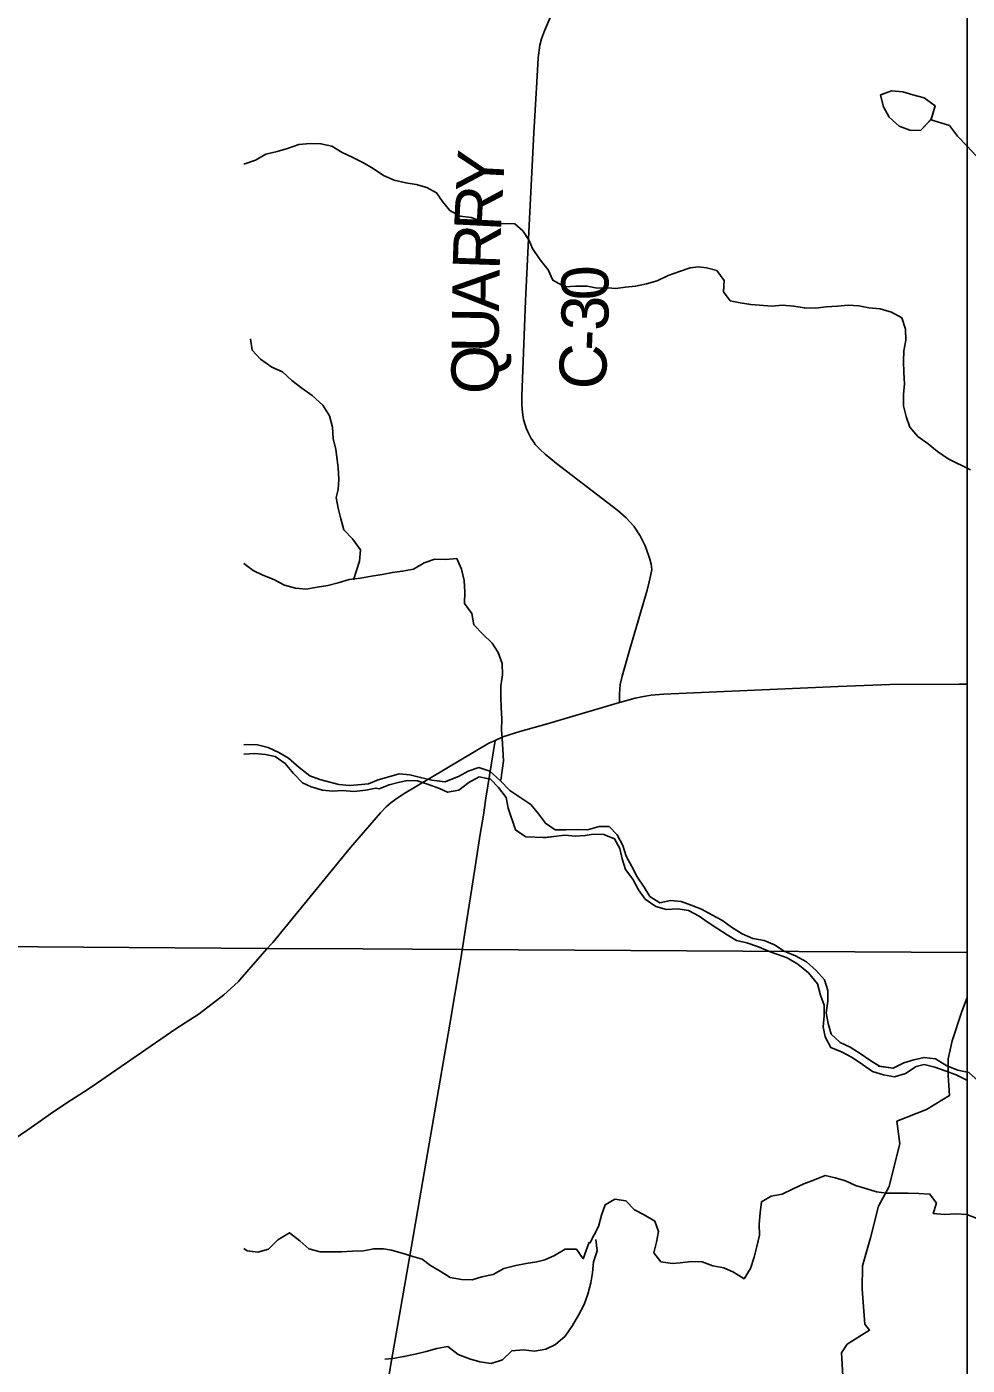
# Model space of a CAD drawing. Extents: x 0 to 34, y 0 to 22.
# Drawn here: x 12.978 to 14.113, y 5.366 to 6.981 of the extents above; entities that cross this region are included whole.
import ezdxf

# ---------------------------------------------------------------- set-up
doc = ezdxf.new("R2010")
doc.units = 0
for name, color, linetype in [('GM_X_Corporation', 7, 'Continuous'), ('GM_X_County_Road', 7, 'Continuous'), ('GM_X_County_Road_Text', 7, 'Continuous'), ('GM_X_Minor_Lake', 7, 'Continuous'), ('GM_X_Minor_River', 7, 'Continuous'), ('GM_X_Rail_Line', 7, 'Continuous'), ('GM_X_State_Route', 7, 'Continuous'), ('SH_Cut_Line', 7, 'Continuous')]:
    doc.layers.add(name, color=color, linetype=linetype)

msp = doc.modelspace()

# ---------------------------------------------------------------- linework, layer by layer
at = {"layer": 'GM_X_Corporation'}
msp.add_lwpolyline([(14.1135, 4.7332), (14.1135, 5.8104), (14.1071, 5.7933), (14.0953, 5.7578), (14.0903, 5.7361), (14.0906, 5.7159), (14.0919, 5.6919), (14.0642, 5.6752), (14.0285, 5.6608), (14.032, 5.6338), (14.0285, 5.6197), (14.0191, 5.5822), (14.0062, 5.5586), (13.9968, 5.5201), (13.9869, 5.4863), (13.9865, 5.4581), (13.9897, 5.416), (13.9956, 5.4089), (13.9686, 5.3919), (13.9616, 5.3814), (13.9633, 5.3538)], dxfattribs=at)
at = {"layer": 'GM_X_County_Road'}
for points in [[(13.5815, 6.4964), (13.5801, 6.5), (13.5779, 6.5076), (13.5765, 6.516), (13.576, 6.5253), (13.576, 6.5362), (13.5803, 6.651), (13.5845, 6.7421), (13.5903, 6.8537), (13.5927, 6.8945), (13.5941, 6.9147), (13.5957, 6.944), (13.5977, 6.9594), (13.5994, 6.9668), (13.603, 6.9764), (13.6163, 7.0074)], [(13.591, 6.4791), (13.587, 6.4847), (13.5829, 6.4928), (13.5815, 6.4964)], [(13.6938, 6.1662), (13.6939, 6.1768), (13.6942, 6.1823), (13.6946, 6.1878), (13.697, 6.1978), (13.7063, 6.2305), (13.727, 6.3017), (13.7297, 6.3116), (13.7316, 6.3205), (13.7326, 6.3267), (13.7319, 6.3329), (13.7304, 6.3389), (13.7288, 6.3441), (13.7247, 6.3553), (13.7185, 6.3673), (13.7109, 6.379), (13.7018, 6.389), (13.6918, 6.3979), (13.6177, 6.4546), (13.6039, 6.4657), (13.598, 6.4716), (13.5921, 6.4774), (13.591, 6.4791)], [(13.5438, 6.1201), (13.553, 6.1246), (13.5733, 6.1311), (13.6052, 6.1399), (13.6553, 6.1547), (13.6938, 6.1662)], [(13.5078, 5.8933), (13.5186, 5.9628), (13.5255, 6.0072), (13.5296, 6.0304), (13.5325, 6.0506), (13.5438, 6.1201)], [(13.502, 5.8567), (13.5038, 5.8675), (13.5078, 5.8933)], [(13.3933, 4.8716), (13.395, 4.9625), (13.3993, 5.1274), (13.4007, 5.1981), (13.4014, 5.2272), (13.4026, 5.2527), (13.404, 5.2742), (13.405, 5.2873), (13.4169, 5.363), (13.4427, 5.51), (13.4888, 5.7781), (13.502, 5.8567)]]:
    msp.add_lwpolyline(points, dxfattribs=at)
at = {"layer": 'GM_X_Minor_Lake'}
for points in [[(14.0699, 6.8698), (14.0746, 6.8862), (14.0616, 6.8957), (14.0479, 6.8994), (14.0357, 6.9031), (14.022, 6.9041), (14.0088, 6.8993)], [(14.0088, 6.8993), (14.0123, 6.885), (14.0192, 6.8725), (14.0311, 6.8616), (14.0441, 6.8567), (14.057, 6.8564), (14.0699, 6.8698)], [(14.0089, 6.8989), (14.0123, 6.885), (14.0192, 6.8725), (14.0311, 6.8616), (14.0441, 6.8567), (14.057, 6.8564), (14.0695, 6.8694)], [(14.0695, 6.8686), (14.0746, 6.8862), (14.0616, 6.8957), (14.0479, 6.8994), (14.0357, 6.9031), (14.022, 6.9041), (14.0091, 6.8994)]]:
    msp.add_lwpolyline(points, dxfattribs=at)
at = {"layer": 'GM_X_Minor_River'}
for points in [[(14.0682, 6.8694), (14.092, 6.8624), (14.1016, 6.8495), (14.1131, 6.8378), (14.1242, 6.8257)], [(13.2404, 6.816), (13.2415, 6.8163), (13.2543, 6.8206), (13.2668, 6.8276), (13.2805, 6.8311), (13.293, 6.8346), (13.3067, 6.8393), (13.3204, 6.8405), (13.3333, 6.8403), (13.3463, 6.8373), (13.3589, 6.8298), (13.3711, 6.8242), (13.3837, 6.8178), (13.3963, 6.8103), (13.4089, 6.802), (13.4219, 6.7964), (13.4356, 6.7931), (13.4482, 6.7913), (13.4612, 6.7876), (13.473, 6.7812), (13.4799, 6.7706), (13.4888, 6.7596), (13.5014, 6.7528), (13.5147, 6.7514), (13.5273, 6.7469), (13.5395, 6.7436), (13.5536, 6.7441), (13.5672, 6.7438), (13.5772, 6.7351), (13.5845, 6.7234), (13.5888, 6.7139), (13.598, 6.7003), (13.6076, 6.6882), (13.6134, 6.6757), (13.6276, 6.6678), (13.6409, 6.6686), (13.6546, 6.6684), (13.6668, 6.6662), (13.6797, 6.6663), (13.6892, 6.6656), (13.701, 6.6672), (13.7132, 6.6684), (13.7261, 6.6712), (13.739, 6.6751), (13.7526, 6.6813), (13.7663, 6.6863), (13.7792, 6.6906), (13.7887, 6.6918), (13.7986, 6.6908), (13.8111, 6.6874), (13.82, 6.6753), (13.8193, 6.6616), (13.8274, 6.651), (13.8392, 6.6485), (13.8522, 6.6463), (13.8781, 6.6442), (13.8902, 6.6454), (13.9039, 6.6444), (13.9169, 6.6422), (13.9302, 6.6419), (13.9431, 6.6435), (13.9568, 6.6444), (13.9697, 6.6456), (13.9826, 6.6446), (13.9948, 6.6424), (14.0082, 6.641), (14.0219, 6.6373), (14.0345, 6.6301), (14.0388, 6.6165), (14.0393, 6.6035)], [(13.2481, 6.6048), (13.2505, 6.5911), (13.2605, 6.5805), (13.2742, 6.5707), (13.2868, 6.5651), (13.298, 6.5545), (13.3102, 6.5455), (13.3228, 6.5364), (13.3355, 6.5251), (13.3436, 6.5122), (13.3471, 6.4985), (13.348, 6.4848), (13.3511, 6.4715), (13.3531, 6.459), (13.3543, 6.4495), (13.3548, 6.4358), (13.3542, 6.4232), (13.3516, 6.4137), (13.354, 6.4008), (13.3575, 6.3879), (13.361, 6.3746), (13.3714, 6.3636), (13.381, 6.3503), (13.38, 6.3366), (13.3728, 6.3141)], [(14.0393, 6.6035), (14.0371, 6.5906), (14.0364, 6.578), (14.0369, 6.5643), (14.0378, 6.5506), (14.0364, 6.5377), (14.0365, 6.524), (14.0396, 6.5114), (14.0443, 6.4985), (14.0539, 6.4872), (14.0661, 6.4781), (14.0776, 6.4691), (14.0906, 6.46), (14.1174, 6.4469)], [(13.2404, 6.3337), (13.2404, 6.3337), (13.2515, 6.3254), (13.2633, 6.3198), (13.2763, 6.3145), (13.2893, 6.3078), (13.3026, 6.3041), (13.3156, 6.303), (13.3289, 6.3054), (13.3418, 6.3074), (13.3543, 6.3106), (13.3672, 6.3145), (13.3809, 6.3161), (13.3942, 6.3185), (13.4071, 6.3205), (13.4196, 6.3232), (13.4318, 6.3245), (13.4451, 6.3269), (13.458, 6.3346), (13.4709, 6.3392), (13.4842, 6.3386), (13.4975, 6.3398), (13.5029, 6.3269), (13.5064, 6.3132), (13.5069, 6.2995), (13.5067, 6.2858), (13.5155, 6.2737), (13.5179, 6.26), (13.5286, 6.2487), (13.5401, 6.2377), (13.5471, 6.2264), (13.5521, 6.2131), (13.5526, 6.1994), (13.5504, 6.1864), (13.5506, 6.1731), (13.551, 6.1602), (13.5515, 6.1465), (13.5513, 6.1328), (13.5521, 6.1233), (13.553, 6.1096), (13.5535, 6.0959), (13.5506, 6.0723)], [(13.4828, 6.0703), (13.4673, 6.0725), (13.4536, 6.0758), (13.4406, 6.0787), (13.4277, 6.0802), (13.4152, 6.0766), (13.4023, 6.0727), (13.3906, 6.0681), (13.378, 6.0669), (13.3678, 6.066), (13.3548, 6.0674), (13.332, 6.0733), (13.3198, 6.0778), (13.3071, 6.0876), (13.2941, 6.0989), (13.2823, 6.1057), (13.2697, 6.112), (13.2567, 6.115), (13.2438, 6.1156), (13.2404, 6.1152)], [(13.4831, 6.0703), (13.4673, 6.0725), (13.4536, 6.0758), (13.4406, 6.0787), (13.4277, 6.0802), (13.4152, 6.0766), (13.4023, 6.0727), (13.3906, 6.0681), (13.378, 6.0669), (13.3678, 6.066), (13.3548, 6.0674), (13.332, 6.0733), (13.3198, 6.0778), (13.3071, 6.0876), (13.2941, 6.0989), (13.2823, 6.1057), (13.2697, 6.112), (13.2567, 6.115), (13.2438, 6.1156), (13.2404, 6.1152)], [(13.2404, 6.1038), (13.2405, 6.1038), (13.2534, 6.1047), (13.2663, 6.1036), (13.2781, 6.1011), (13.29, 6.0924), (13.3, 6.0803), (13.3111, 6.0694), (13.3214, 6.0645), (13.3351, 6.0604), (13.3477, 6.059), (13.3595, 6.0599), (13.3731, 6.0588), (13.3876, 6.0605), (13.3997, 6.0628), (13.4035, 6.0621), (13.4157, 6.0668), (13.4282, 6.0699), (13.4377, 6.0719), (13.4498, 6.0716), (13.4632, 6.0671), (13.4765, 6.0623), (13.4861, 6.0578), (13.4997, 6.0602), (13.5118, 6.0698), (13.5243, 6.0763), (13.538, 6.0738), (13.5476, 6.0636), (13.5568, 6.0515), (13.5592, 6.0386), (13.5682, 6.0124), (13.5808, 6.0042), (13.6026, 6.0031)], [(13.2404, 6.1038), (13.2405, 6.1038), (13.2534, 6.1047), (13.2663, 6.1036), (13.2781, 6.1011), (13.29, 6.0924), (13.3, 6.0803), (13.3111, 6.0694), (13.3214, 6.0645), (13.3351, 6.0604), (13.3477, 6.059), (13.3595, 6.0599), (13.3731, 6.0588), (13.3876, 6.0605), (13.3997, 6.0628), (13.4035, 6.0621), (13.4157, 6.0668), (13.4282, 6.0699), (13.4377, 6.0719), (13.4498, 6.0716), (13.4632, 6.0671), (13.4765, 6.0623), (13.4861, 6.0578), (13.4997, 6.0602), (13.5118, 6.0698), (13.5243, 6.0763), (13.538, 6.0738), (13.5476, 6.0636), (13.5568, 6.0515), (13.5592, 6.0386), (13.5682, 6.0124), (13.5808, 6.0042), (13.6026, 6.0031)], [(14.0075, 5.7273), (13.996, 5.7345), (13.9842, 5.7428), (13.9723, 5.7503), (13.9601, 5.7559), (13.9494, 5.7661), (13.9454, 5.779), (13.943, 5.7919), (13.9452, 5.8056), (13.9451, 5.8185), (13.9412, 5.8314), (13.9312, 5.8427), (13.9193, 5.8533), (13.9063, 5.8604), (13.8926, 5.866), (13.8807, 5.8739), (13.8682, 5.8791), (13.8548, 5.8813), (13.8419, 5.8869), (13.83, 5.8941), (13.8174, 5.9035), (13.8052, 5.9098), (13.7926, 5.9166), (13.7803, 5.9218), (13.7681, 5.9259), (13.7552, 5.9273), (13.7423, 5.9246), (13.7304, 5.9321), (13.7235, 5.9434), (13.715, 5.9559), (13.7085, 5.9684), (13.7019, 5.9809), (13.6976, 5.9938), (13.691, 6.0063), (13.6814, 6.0165), (13.6693, 6.0164), (13.6552, 6.0125), (13.6427, 6.0131), (13.629, 6.0127), (13.6161, 6.0126), (13.6042, 6.0204), (13.5961, 6.0318), (13.5865, 6.0431), (13.5735, 6.0521), (13.5613, 6.06), (13.5502, 6.0717), (13.5371, 6.0834), (13.5238, 6.0879), (13.5109, 6.0832), (13.4992, 6.077), (13.4828, 6.0703)], [(14.0079, 5.727), (13.996, 5.7345), (13.9842, 5.7428), (13.9723, 5.7503), (13.9601, 5.7559), (13.9494, 5.7661), (13.9454, 5.779), (13.943, 5.7919), (13.9452, 5.8056), (13.9451, 5.8185), (13.9412, 5.8314), (13.9312, 5.8427), (13.9193, 5.8533), (13.9063, 5.8604), (13.8926, 5.866), (13.8807, 5.8739), (13.8682, 5.8791), (13.8548, 5.8813), (13.8419, 5.8869), (13.83, 5.8941), (13.8174, 5.9035), (13.8052, 5.9098), (13.7926, 5.9166), (13.7803, 5.9218), (13.7681, 5.9259), (13.7552, 5.9273), (13.7423, 5.9246), (13.7304, 5.9321), (13.7235, 5.9434), (13.715, 5.9559), (13.7085, 5.9684), (13.7019, 5.9809), (13.6976, 5.9938), (13.691, 6.0063), (13.6814, 6.0165), (13.6693, 6.0164), (13.6552, 6.0125), (13.6427, 6.0131), (13.629, 6.0127), (13.6161, 6.0126), (13.6042, 6.0204), (13.5961, 6.0318), (13.5865, 6.0431), (13.5735, 6.0521), (13.5613, 6.06), (13.5502, 6.0717), (13.5371, 6.0834), (13.5238, 6.0879), (13.5109, 6.0832), (13.4992, 6.077), (13.4834, 6.0705)], [(13.6021, 6.0028), (13.6146, 6.0044), (13.6276, 6.006), (13.6405, 6.005), (13.6523, 6.0055), (13.6618, 6.0071), (13.6747, 6.0068), (13.6877, 6.0015), (13.6942, 5.9898), (13.697, 5.9777), (13.7009, 5.9648), (13.7098, 5.9531), (13.7167, 5.9402), (13.7248, 5.9288), (13.7374, 5.9202), (13.7504, 5.9165), (13.7641, 5.917), (13.777, 5.9152), (13.79, 5.9084), (13.7995, 5.9017), (13.8114, 5.8938), (13.8236, 5.8859), (13.8351, 5.8791), (13.8473, 5.8762), (13.8603, 5.8717), (13.8769, 5.8649)], [(13.6026, 6.0031), (13.6146, 6.0044), (13.6276, 6.006), (13.6405, 6.005), (13.6523, 6.0055), (13.6618, 6.0071), (13.6747, 6.0068), (13.6877, 6.0015), (13.6942, 5.9898), (13.697, 5.9777), (13.7009, 5.9648), (13.7098, 5.9531), (13.7167, 5.9402), (13.7248, 5.9288), (13.7374, 5.9202), (13.7504, 5.9165), (13.7641, 5.917), (13.777, 5.9152), (13.79, 5.9084), (13.7995, 5.9017), (13.8114, 5.8938), (13.8236, 5.8859), (13.8351, 5.8791), (13.8473, 5.8762), (13.8603, 5.8717), (13.8767, 5.8648)], [(13.8767, 5.8648), (13.8961, 5.8579), (13.9091, 5.8504), (13.9217, 5.8399), (13.9329, 5.8266), (13.9364, 5.813), (13.9407, 5.8009), (13.9408, 5.7879), (13.9394, 5.775), (13.9418, 5.7629), (13.9488, 5.75), (13.9625, 5.7444), (13.9747, 5.738), (13.987, 5.7294), (13.9992, 5.7211), (14.0125, 5.717), (14.0255, 5.7145), (14.0391, 5.7184), (14.052, 5.7268), (14.0615, 5.7292), (14.0744, 5.7262), (14.087, 5.7218), (14.1, 5.7169), (14.1137, 5.7102)], [(13.8767, 5.8648), (13.8961, 5.8579), (13.9091, 5.8504), (13.9217, 5.8399), (13.9329, 5.8266), (13.9364, 5.813), (13.9407, 5.8009), (13.9408, 5.7879), (13.9394, 5.775), (13.9418, 5.7629), (13.9488, 5.75), (13.9625, 5.7444), (13.9747, 5.738), (13.987, 5.7294), (13.9992, 5.7211), (14.0125, 5.717), (14.0255, 5.7145), (14.0391, 5.7184), (14.052, 5.7268), (14.0615, 5.7292), (14.0744, 5.7262), (14.087, 5.7218), (14.1, 5.7169), (14.1137, 5.7102)], [(14.2513, 5.6375), (14.2382, 5.6427), (14.2287, 5.6453), (14.2161, 5.6494), (14.2035, 5.6577), (14.1902, 5.6625), (14.1768, 5.6696), (14.1646, 5.6779), (14.1515, 5.6884), (14.1393, 5.6994), (14.1266, 5.7095), (14.1152, 5.7197), (14.1022, 5.7226), (14.0888, 5.7279), (14.0751, 5.7361), (14.0614, 5.7379), (14.0489, 5.7348), (14.0371, 5.7313), (14.0242, 5.7251), (14.0061, 5.7274)], [(14.2512, 5.6374), (14.2382, 5.6427), (14.2287, 5.6453), (14.2161, 5.6494), (14.2035, 5.6577), (14.1902, 5.6625), (14.1768, 5.6696), (14.1646, 5.6779), (14.1515, 5.6884), (14.1393, 5.6994), (14.1266, 5.7095), (14.1152, 5.7197), (14.1022, 5.7226), (14.0888, 5.7279), (14.0751, 5.7361), (14.0614, 5.7379), (14.0489, 5.7348), (14.0371, 5.7313), (14.0242, 5.7251), (14.0075, 5.7273)], [(13.6578, 5.5138), (13.6682, 5.5338), (13.6719, 5.5475), (13.6763, 5.5601), (13.6881, 5.5667), (13.7014, 5.5649), (13.7117, 5.5539), (13.7236, 5.5479), (13.7362, 5.5404), (13.7409, 5.5279), (13.7383, 5.515), (13.735, 5.502), (13.7438, 5.4911), (13.7576, 5.4893), (13.767, 5.4901), (13.7803, 5.4917), (13.7933, 5.4914), (13.8062, 5.4866), (13.8196, 5.484), (13.8314, 5.4788), (13.844, 5.4709), (13.8519, 5.4831), (13.8563, 5.4969), (13.8593, 5.5098), (13.8626, 5.5235), (13.8624, 5.5368), (13.8635, 5.5505), (13.8652, 5.5638), (13.8766, 5.5704), (13.8902, 5.5731), (13.9035, 5.5793), (13.9164, 5.5855), (13.9289, 5.5902), (13.9418, 5.5956), (13.9539, 5.5926), (13.9665, 5.5889), (13.9784, 5.5833), (13.9921, 5.5792), (14.0039, 5.5759), (14.0161, 5.5741), (14.0423, 5.5743), (14.0552, 5.5736), (14.0685, 5.573), (14.0762, 5.562), (14.0725, 5.5494), (14.0859, 5.5484), (14.0995, 5.5493), (14.1129, 5.5482), (14.1254, 5.5434)], [(13.2404, 5.5072), (13.2442, 5.5044), (13.2571, 5.503), (13.27, 5.5065), (13.2813, 5.518), (13.2953, 5.5264), (13.308, 5.5166), (13.3187, 5.5068), (13.3324, 5.5035), (13.3453, 5.5032), (13.3583, 5.5033), (13.3716, 5.5042), (13.3845, 5.5047), (13.397, 5.5071), (13.4088, 5.5068), (13.4183, 5.5053), (13.4313, 5.5016), (13.4442, 5.4975), (13.4557, 5.4946), (13.4656, 5.487), (13.4771, 5.4799), (13.4893, 5.4724), (13.503, 5.4698), (13.5159, 5.4696), (13.5277, 5.4731), (13.5414, 5.4758), (13.5542, 5.4832), (13.5686, 5.4867), (13.5812, 5.4894), (13.5941, 5.4914), (13.6035, 5.4938), (13.6153, 5.4988), (13.6281, 5.5065), (13.6418, 5.5066), (13.6499, 5.4949), (13.6572, 5.5149)], [(13.4106, 5.3738), (13.4201, 5.3747), (13.4334, 5.377), (13.447, 5.3798), (13.4603, 5.383), (13.4732, 5.3865), (13.4865, 5.3892), (13.4991, 5.3794), (13.5125, 5.3742), (13.5251, 5.3705), (13.5388, 5.3687), (13.5524, 5.373), (13.5638, 5.3837), (13.5774, 5.385), (13.5912, 5.3836), (13.6048, 5.386), (13.6166, 5.3914), (13.6283, 5.4017), (13.6369, 5.4144), (13.6444, 5.427), (13.6512, 5.4396), (13.6556, 5.4522), (13.659, 5.4659), (13.6611, 5.4781), (13.6622, 5.4914), (13.6666, 5.5044), (13.665, 5.5181)]]:
    msp.add_lwpolyline(points, dxfattribs=at)
at = {"layer": 'GM_X_Rail_Line'}
for points in [[(14.1135, 5.8645), (14.1135, 10.4074), (12.9952, 10.4123), (12.9843, 9.8218), (12.975, 9.4666), (12.9697, 9.2637), (12.9695, 9.2552), (12.9694, 9.2509), (12.9542, 8.6724), (12.9304, 7.7644), (12.9222, 7.4711), (12.9186, 7.3231), (12.9183, 7.3117), (12.9181, 7.3048), (12.8807, 5.8723), (13.2678, 5.8695), (13.384, 5.8688), (13.5036, 5.8681)], [(12.8629, 3.6647), (14.1135, 3.6647), (14.1135, 5.8645), (13.5036, 5.8681), (13.384, 5.8688), (13.2678, 5.8695), (12.8807, 5.8723), (12.8785, 5.5987), (12.8728, 4.8847)]]:
    msp.add_lwpolyline(points, close=True, dxfattribs=at)
at = {"layer": 'GM_X_State_Route'}
for points in [[(13.6938, 6.1662), (13.7127, 6.1714), (13.7227, 6.1733), (13.732, 6.175), (13.747, 6.1764), (13.9575, 6.1855), (14.0206, 6.1879), (14.1039, 6.1884), (14.1135, 6.1884)], [(13.5438, 6.1201), (13.553, 6.1246), (13.5733, 6.1311), (13.6052, 6.1399), (13.6553, 6.1547), (13.6938, 6.1662)], [(13.2733, 5.8745), (13.2752, 5.8766), (13.369, 5.9912), (13.4052, 6.033), (13.4122, 6.0404), (13.4176, 6.0452), (13.4238, 6.0495), (13.4324, 6.0554), (13.536, 6.117), (13.5438, 6.1201)], [(13.2333, 5.8293), (13.2356, 5.8314), (13.268, 5.8689), (13.2733, 5.8745)], [(13.0624, 5.7064), (13.1582, 5.7723), (13.1862, 5.7904), (13.2163, 5.8134), (13.2333, 5.8293)], [(12.9, 5.6062), (12.9019, 5.6069), (12.9264, 5.6174), (12.9436, 5.627), (12.9618, 5.6384), (12.9797, 5.6504), (12.9914, 5.659), (13.0069, 5.6697), (13.0267, 5.6831), (13.0525, 5.6995), (13.0624, 5.7064)]]:
    msp.add_lwpolyline(points, dxfattribs=at)
at = {"layer": 'SH_Cut_Line'}
msp.add_lwpolyline([(8.8581, 3.6647), (14.1135, 3.6647), (14.1135, 10.4647), (8.6408, 10.4647)], dxfattribs=at)

# ---------------------------------------------------------------- texts
at = {"layer": 'GM_X_County_Road_Text'}
for s, rotation, p in [('Y', 86.9495, (13.5529, 6.7806)), ('R', 87.1614, (13.5506, 6.734)), ('R', 88.1028, (13.549, 6.6876)), ('A', 89.1184, (13.5483, 6.6379)), ('0', 91.2668, (13.6808, 6.6521)), ('3', 88.8004, (13.68, 6.6144)), ('U', 89.4281, (13.5478, 6.588)), ('-', 87.5998, (13.679, 6.5898)), ('Q', 89.4317, (13.5473, 6.538)), ('C', 87.1887, (13.6767, 6.5428))]:
    msp.add_text(s, height=0.0568, rotation=rotation, dxfattribs=at).set_placement(p)

doc.saveas('drawing.dxf')
